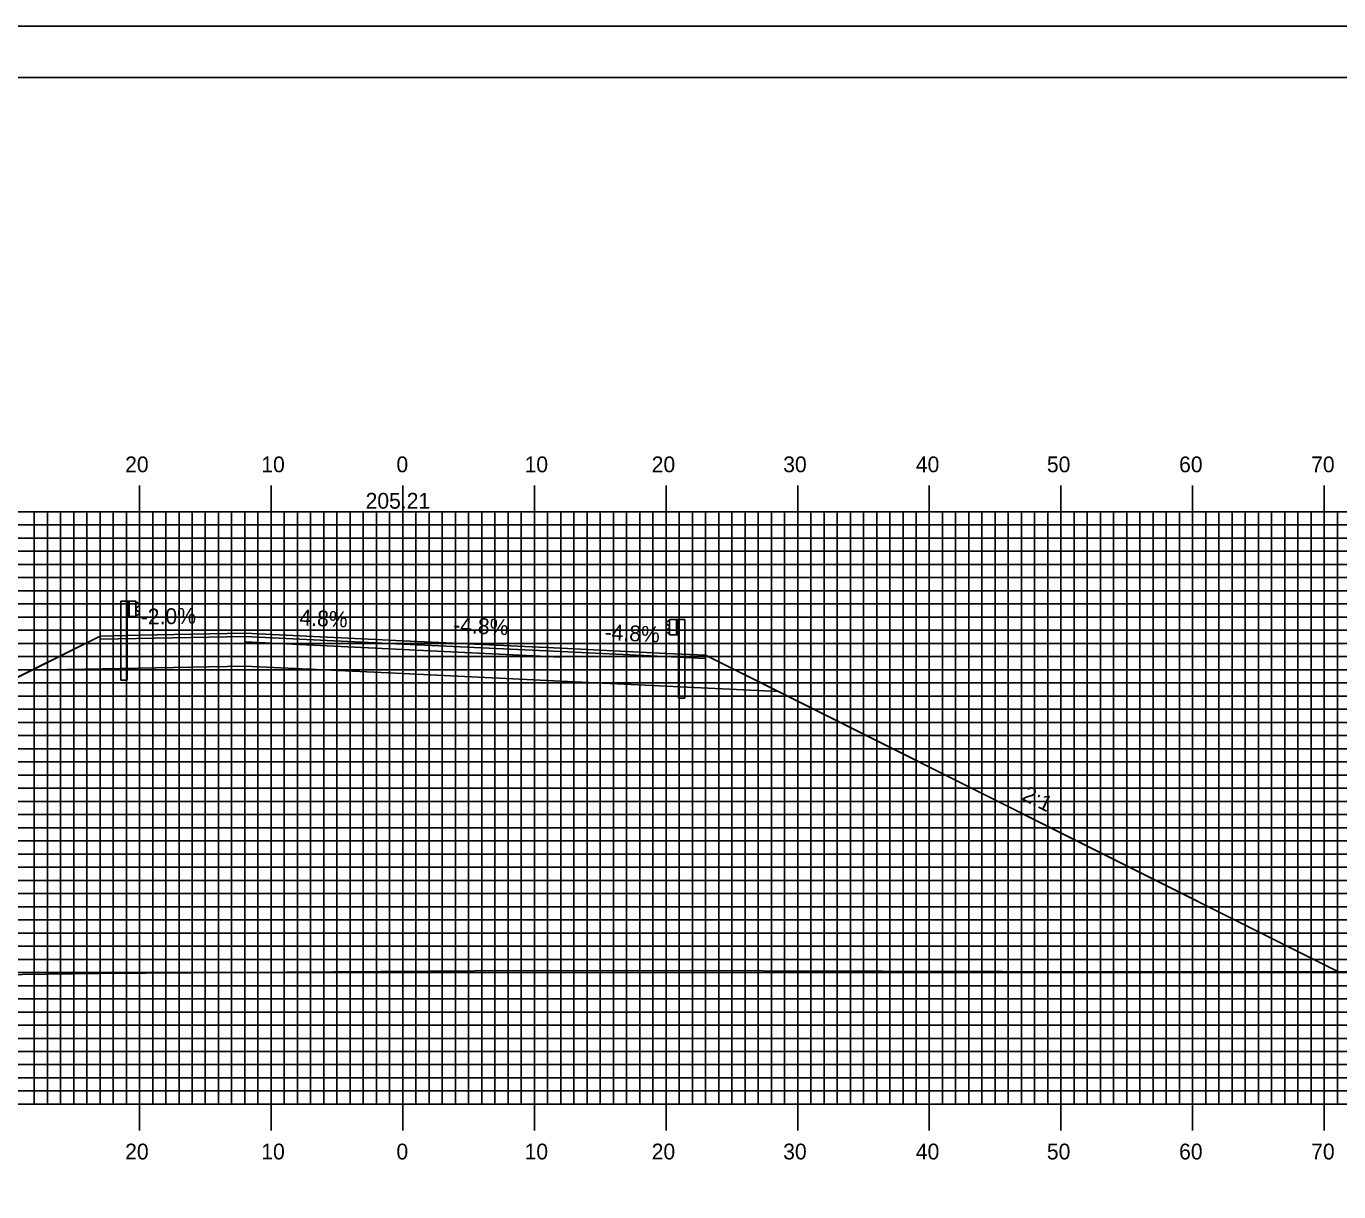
# Model space of a CAD drawing. Extents: x 1809406 to 1809749, y 442591 to 442811.
# Drawn here: x 1809543.2 to 1809642.9, y 442722 to 442810.5 of the extents above; entities that cross this region are included whole.
import ezdxf

# ---------------------------------------------------------------- set-up
doc = ezdxf.new("R2010")
doc.units = 0
for name, color, linetype in [('ANNOTATION', 7, 'Continuous'), ('BORDER', 7, 'Continuous'), ('D_Guardrail_Beam_Lt', 7, 'Continuous'), ('D_Guardrail_Beam_Rt', 7, 'Continuous'), ('D_Roadway_Centerline', 7, 'Continuous'), ('D_Roadway_Centerline_Text', 7, 'Continuous'), ('D_Roadway_Edge_Shoulder', 7, 'Continuous'), ('D_Roadway_Edge_TW', 7, 'Continuous'), ('D_Roadway_Pavement', 7, 'Continuous'), ('D_Roadway_SlopeLines', 7, 'Continuous'), ('D_Roadway_SubGrade', 7, 'Continuous'), ('H_V ANNOTATION', 7, 'Continuous'), ('MAJOR', 7, 'Continuous'), ('MINOR', 7, 'Continuous'), ('PLOT BOUNDARY', 7, 'Continuous'), ('S_Roadway_Centerline', 7, 'Continuous')]:
    doc.layers.add(name, color=color, linetype=linetype)

msp = doc.modelspace()

# ---------------------------------------------------------------- linework, layer by layer
at = {"layer": 'BORDER'}
msp.add_lwpolyline([(1809422.237, 442596.665), (1809742.237, 442596.665), (1809742.237, 442806.665), (1809422.237, 442806.665)], close=True, dxfattribs=at)
at = {"layer": 'D_Guardrail_Beam_Lt'}
for p, q in [((1809550.408, 442766.87), (1809550.408, 442760.87)), ((1809550.879, 442766.87), (1809550.408, 442766.87)), ((1809551.566, 442766.87), (1809550.879, 442766.87)), ((1809550.879, 442766.87), (1809550.879, 442765.703)), ((1809550.941, 442766.87), (1809550.941, 442765.703)), ((1809551.046, 442766.87), (1809551.046, 442765.703)), ((1809551.566, 442765.703), (1809551.566, 442766.87)), ((1809551.566, 442766.786), (1809551.641, 442766.772)), ((1809551.8, 442766.522), (1809551.605, 442766.386)), ((1809551.656, 442766.765), (1809551.8, 442766.665)), ((1809550.879, 442765.703), (1809551.566, 442765.703)), ((1809550.9, 442760.87), (1809550.9, 442765.703)), ((1809551.641, 442765.801), (1809551.566, 442765.786)), ((1809551.571, 442766.321), (1809551.571, 442766.251)), ((1809551.605, 442766.187), (1809551.8, 442766.051)), ((1809551.8, 442765.907), (1809551.656, 442765.807)), ((1809550.9, 442760.87), (1809550.408, 442760.87))]:
    msp.add_line(p, q, dxfattribs=at)
for centre, major_axis, start_param, end_param in [((1809551.633, 442766.731), (0.0417, 0), 0.959931, 1.376053), ((1809551.75, 442766.593), (0.0877, 0), 5.323254, 7.243116), ((1809551.65, 442766.321), (-0.0789, 0), 5.323254, 6.283185), ((1809551.65, 442766.251), (-0.0789, 0), 6.283185, 7.243116), ((1809551.633, 442765.841), (0.0417, 0), 4.907132, 5.323254), ((1809551.75, 442765.979), (0.0877, 0), 5.323254, 7.243116)]:
    msp.add_ellipse(centre, major_axis=major_axis, ratio=0.995501, start_param=start_param, end_param=end_param, dxfattribs=at)
at = {"layer": 'D_Guardrail_Beam_Rt'}
for p, q in [((1809592.018, 442765.389), (1809591.875, 442765.289)), ((1809591.875, 442765.146), (1809592.07, 442765.01)), ((1809592.07, 442764.811), (1809591.875, 442764.675)), ((1809591.875, 442764.531), (1809592.018, 442764.431)), ((1809592.108, 442765.41), (1809592.034, 442765.396)), ((1809592.104, 442764.945), (1809592.104, 442764.875)), ((1809592.108, 442765.494), (1809592.796, 442765.494)), ((1809592.108, 442764.327), (1809592.108, 442765.494)), ((1809592.629, 442765.494), (1809592.629, 442764.327)), ((1809592.733, 442765.494), (1809592.733, 442764.327)), ((1809592.796, 442765.494), (1809593.266, 442765.494)), ((1809592.796, 442765.494), (1809592.796, 442764.327)), ((1809593.266, 442765.494), (1809593.266, 442759.494)), ((1809592.034, 442764.425), (1809592.108, 442764.41)), ((1809592.796, 442764.327), (1809592.108, 442764.327)), ((1809592.775, 442759.494), (1809592.775, 442764.327)), ((1809592.775, 442759.494), (1809593.266, 442759.494))]:
    msp.add_line(p, q, dxfattribs=at)
for centre, major_axis, start_param, end_param in [((1809591.925, 442765.217), (-0.0877, 0), 5.323254, 7.243116), ((1809591.925, 442764.603), (-0.0877, 0), 5.323254, 7.243116), ((1809592.042, 442765.355), (-0.0417, 0), 4.907132, 5.323254), ((1809592.025, 442764.945), (0.0789, 0), 0, 0.959931), ((1809592.025, 442764.875), (0.0789, 0), 5.323254, 6.283185), ((1809592.042, 442764.465), (-0.0417, 0), 0.959931, 1.376053)]:
    msp.add_ellipse(centre, major_axis=major_axis, ratio=0.995501, start_param=start_param, end_param=end_param, dxfattribs=at)
at = {"layer": 'D_Roadway_Centerline'}
msp.add_lwpolyline([(1809497.104, 442738.36), (1809543.629, 442761.622), (1809548.837, 442764.226), (1809551.837, 442764.286), (1809559.837, 442764.446), (1809571.837, 442763.87), (1809583.837, 442763.294), (1809591.837, 442762.91), (1809594.837, 442762.766), (1809600.368, 442760.001), (1809642.88, 442738.745)], dxfattribs=at)
at = {"layer": 'D_Roadway_Edge_Shoulder'}
for points in [[(1809559.837, 442764.446), (1809551.837, 442764.286), (1809551.837, 442764.286), (1809548.837, 442764.226), (1809548.837, 442763.976), (1809559.837, 442764.196)], [(1809583.837, 442763.294), (1809591.837, 442762.91), (1809591.837, 442762.91), (1809594.837, 442762.766), (1809594.837, 442762.516), (1809583.837, 442763.044)]]:
    msp.add_lwpolyline(points, close=True, dxfattribs=at)
at = {"layer": 'D_Roadway_Edge_TW'}
msp.add_lwpolyline([(1809559.837, 442764.196), (1809559.837, 442764.446), (1809571.837, 442763.87), (1809583.837, 442763.294), (1809583.837, 442763.044), (1809571.837, 442763.62)], close=True, dxfattribs=at)
at = {"layer": 'D_Roadway_Pavement'}
msp.add_lwpolyline([(1809559.837, 442763.78), (1809559.837, 442764.196), (1809571.837, 442763.62), (1809583.837, 442763.044), (1809583.837, 442762.628), (1809571.837, 442763.204)], close=True, dxfattribs=at)
for points in [[(1809559.837, 442764.196), (1809559.837, 442763.78)], [(1809583.837, 442763.044), (1809583.837, 442762.628)]]:
    msp.add_lwpolyline(points, dxfattribs=at)
at = {"layer": 'D_Roadway_SlopeLines'}
for points in [[(1809548.837, 442764.226), (1809497.104, 442738.36)], [(1809594.837, 442762.766), (1809642.88, 442738.745)]]:
    msp.add_lwpolyline(points, dxfattribs=at)
at = {"layer": 'D_Roadway_SubGrade'}
for points in [[(1809559.837, 442763.78), (1809559.837, 442764.196), (1809548.837, 442763.976), (1809548.837, 442764.226), (1809543.629, 442761.622), (1809559.837, 442761.946)], [(1809559.837, 442761.946), (1809559.837, 442764.196), (1809559.837, 442763.78), (1809571.837, 442763.204), (1809583.837, 442762.628), (1809583.837, 442763.044), (1809583.837, 442760.794), (1809571.837, 442761.37)], [(1809583.837, 442762.628), (1809583.837, 442763.044), (1809594.837, 442762.516), (1809594.837, 442762.766), (1809600.368, 442760.001), (1809583.837, 442760.794)]]:
    msp.add_lwpolyline(points, close=True, dxfattribs=at)
at = {"layer": 'MAJOR'}
for p, q in [((1809551.837, 442775.669), (1809551.837, 442773.665)), ((1809561.837, 442775.669), (1809561.837, 442773.665)), ((1809571.837, 442775.669), (1809571.837, 442773.665)), ((1809581.837, 442775.669), (1809581.837, 442773.665)), ((1809591.837, 442775.669), (1809591.837, 442773.665)), ((1809601.837, 442775.669), (1809601.837, 442773.665)), ((1809611.837, 442775.669), (1809611.837, 442773.665)), ((1809621.837, 442775.669), (1809621.837, 442773.665)), ((1809631.837, 442775.669), (1809631.837, 442773.665)), ((1809641.837, 442775.669), (1809641.837, 442773.665)), ((1809431.837, 442773.665), (1809711.837, 442773.665)), ((1809431.837, 442773.665), (1809711.837, 442773.665)), ((1809551.837, 442728.665), (1809551.837, 442773.665)), ((1809561.837, 442728.665), (1809561.837, 442773.665)), ((1809571.837, 442728.665), (1809571.837, 442773.665)), ((1809581.837, 442728.665), (1809581.837, 442773.665)), ((1809591.837, 442728.665), (1809591.837, 442773.665)), ((1809601.837, 442728.665), (1809601.837, 442773.665)), ((1809611.837, 442728.665), (1809611.837, 442773.665)), ((1809621.837, 442728.665), (1809621.837, 442773.665)), ((1809631.837, 442728.665), (1809631.837, 442773.665)), ((1809641.837, 442728.665), (1809641.837, 442773.665)), ((1809431.837, 442768.665), (1809711.837, 442768.665)), ((1809431.837, 442763.665), (1809711.837, 442763.665)), ((1809431.837, 442758.665), (1809711.837, 442758.665)), ((1809431.837, 442753.665), (1809711.837, 442753.665)), ((1809431.837, 442748.665), (1809711.837, 442748.665)), ((1809431.837, 442743.665), (1809711.837, 442743.665)), ((1809431.837, 442738.665), (1809711.837, 442738.665)), ((1809431.837, 442733.665), (1809711.837, 442733.665)), ((1809431.837, 442728.665), (1809711.837, 442728.665)), ((1809431.837, 442728.665), (1809711.837, 442728.665)), ((1809551.837, 442726.661), (1809551.837, 442728.665)), ((1809561.837, 442726.661), (1809561.837, 442728.665)), ((1809571.837, 442726.661), (1809571.837, 442728.665)), ((1809581.837, 442726.661), (1809581.837, 442728.665)), ((1809591.837, 442726.661), (1809591.837, 442728.665)), ((1809601.837, 442726.661), (1809601.837, 442728.665)), ((1809611.837, 442726.661), (1809611.837, 442728.665)), ((1809621.837, 442726.661), (1809621.837, 442728.665)), ((1809631.837, 442726.661), (1809631.837, 442728.665)), ((1809641.837, 442726.661), (1809641.837, 442728.665))]:
    msp.add_line(p, q, dxfattribs=at)
at = {"layer": 'MINOR'}
for p, q in [((1809543.837, 442728.665), (1809543.837, 442773.665)), ((1809544.837, 442728.665), (1809544.837, 442773.665)), ((1809545.837, 442728.665), (1809545.837, 442773.665)), ((1809546.837, 442728.665), (1809546.837, 442773.665)), ((1809547.837, 442728.665), (1809547.837, 442773.665)), ((1809548.837, 442728.665), (1809548.837, 442773.665)), ((1809549.837, 442728.665), (1809549.837, 442773.665)), ((1809550.837, 442728.665), (1809550.837, 442773.665)), ((1809552.837, 442728.665), (1809552.837, 442773.665)), ((1809553.837, 442728.665), (1809553.837, 442773.665)), ((1809554.837, 442728.665), (1809554.837, 442773.665)), ((1809555.837, 442728.665), (1809555.837, 442773.665)), ((1809556.837, 442728.665), (1809556.837, 442773.665)), ((1809557.837, 442728.665), (1809557.837, 442773.665)), ((1809558.837, 442728.665), (1809558.837, 442773.665)), ((1809559.837, 442728.665), (1809559.837, 442773.665)), ((1809560.837, 442728.665), (1809560.837, 442773.665)), ((1809562.837, 442728.665), (1809562.837, 442773.665)), ((1809563.837, 442728.665), (1809563.837, 442773.665)), ((1809564.837, 442728.665), (1809564.837, 442773.665)), ((1809565.837, 442728.665), (1809565.837, 442773.665)), ((1809566.837, 442728.665), (1809566.837, 442773.665)), ((1809567.837, 442728.665), (1809567.837, 442773.665)), ((1809568.837, 442728.665), (1809568.837, 442773.665)), ((1809569.837, 442728.665), (1809569.837, 442773.665)), ((1809570.837, 442728.665), (1809570.837, 442773.665)), ((1809572.837, 442728.665), (1809572.837, 442773.665)), ((1809573.837, 442728.665), (1809573.837, 442773.665)), ((1809574.837, 442728.665), (1809574.837, 442773.665)), ((1809575.837, 442728.665), (1809575.837, 442773.665)), ((1809576.837, 442728.665), (1809576.837, 442773.665)), ((1809577.837, 442728.665), (1809577.837, 442773.665)), ((1809578.837, 442728.665), (1809578.837, 442773.665)), ((1809579.837, 442728.665), (1809579.837, 442773.665)), ((1809580.837, 442728.665), (1809580.837, 442773.665)), ((1809582.837, 442728.665), (1809582.837, 442773.665)), ((1809583.837, 442728.665), (1809583.837, 442773.665)), ((1809584.837, 442728.665), (1809584.837, 442773.665)), ((1809585.837, 442728.665), (1809585.837, 442773.665)), ((1809586.837, 442728.665), (1809586.837, 442773.665)), ((1809587.837, 442728.665), (1809587.837, 442773.665)), ((1809588.837, 442728.665), (1809588.837, 442773.665)), ((1809589.837, 442728.665), (1809589.837, 442773.665)), ((1809590.837, 442728.665), (1809590.837, 442773.665)), ((1809592.837, 442728.665), (1809592.837, 442773.665)), ((1809593.837, 442728.665), (1809593.837, 442773.665)), ((1809594.837, 442728.665), (1809594.837, 442773.665)), ((1809595.837, 442728.665), (1809595.837, 442773.665)), ((1809596.837, 442728.665), (1809596.837, 442773.665)), ((1809597.837, 442728.665), (1809597.837, 442773.665)), ((1809598.837, 442728.665), (1809598.837, 442773.665)), ((1809599.837, 442728.665), (1809599.837, 442773.665)), ((1809600.837, 442728.665), (1809600.837, 442773.665)), ((1809602.837, 442728.665), (1809602.837, 442773.665)), ((1809603.837, 442728.665), (1809603.837, 442773.665)), ((1809604.837, 442728.665), (1809604.837, 442773.665)), ((1809605.837, 442728.665), (1809605.837, 442773.665)), ((1809606.837, 442728.665), (1809606.837, 442773.665)), ((1809607.837, 442728.665), (1809607.837, 442773.665)), ((1809608.837, 442728.665), (1809608.837, 442773.665)), ((1809609.837, 442728.665), (1809609.837, 442773.665)), ((1809610.837, 442728.665), (1809610.837, 442773.665)), ((1809612.837, 442728.665), (1809612.837, 442773.665)), ((1809613.837, 442728.665), (1809613.837, 442773.665)), ((1809614.837, 442728.665), (1809614.837, 442773.665)), ((1809615.837, 442728.665), (1809615.837, 442773.665)), ((1809616.837, 442728.665), (1809616.837, 442773.665)), ((1809617.837, 442728.665), (1809617.837, 442773.665)), ((1809618.837, 442728.665), (1809618.837, 442773.665)), ((1809619.837, 442728.665), (1809619.837, 442773.665)), ((1809620.837, 442728.665), (1809620.837, 442773.665)), ((1809622.837, 442728.665), (1809622.837, 442773.665)), ((1809623.837, 442728.665), (1809623.837, 442773.665)), ((1809624.837, 442728.665), (1809624.837, 442773.665)), ((1809625.837, 442728.665), (1809625.837, 442773.665)), ((1809626.837, 442728.665), (1809626.837, 442773.665)), ((1809627.837, 442728.665), (1809627.837, 442773.665)), ((1809628.837, 442728.665), (1809628.837, 442773.665)), ((1809629.837, 442728.665), (1809629.837, 442773.665)), ((1809630.837, 442728.665), (1809630.837, 442773.665)), ((1809632.837, 442728.665), (1809632.837, 442773.665)), ((1809633.837, 442728.665), (1809633.837, 442773.665)), ((1809634.837, 442728.665), (1809634.837, 442773.665)), ((1809635.837, 442728.665), (1809635.837, 442773.665)), ((1809636.837, 442728.665), (1809636.837, 442773.665)), ((1809637.837, 442728.665), (1809637.837, 442773.665)), ((1809638.837, 442728.665), (1809638.837, 442773.665)), ((1809639.837, 442728.665), (1809639.837, 442773.665)), ((1809640.837, 442728.665), (1809640.837, 442773.665)), ((1809642.837, 442728.665), (1809642.837, 442773.665)), ((1809431.837, 442772.665), (1809711.837, 442772.665)), ((1809431.837, 442771.665), (1809711.837, 442771.665)), ((1809431.837, 442770.665), (1809711.837, 442770.665)), ((1809431.837, 442769.665), (1809711.837, 442769.665)), ((1809431.837, 442767.665), (1809711.837, 442767.665)), ((1809431.837, 442766.665), (1809711.837, 442766.665)), ((1809431.837, 442765.665), (1809711.837, 442765.665)), ((1809431.837, 442764.665), (1809711.837, 442764.665)), ((1809431.837, 442762.665), (1809711.837, 442762.665)), ((1809431.837, 442761.665), (1809711.837, 442761.665)), ((1809431.837, 442760.665), (1809711.837, 442760.665)), ((1809431.837, 442759.665), (1809711.837, 442759.665)), ((1809431.837, 442757.665), (1809711.837, 442757.665)), ((1809431.837, 442756.665), (1809711.837, 442756.665)), ((1809431.837, 442755.665), (1809711.837, 442755.665)), ((1809431.837, 442754.665), (1809711.837, 442754.665)), ((1809431.837, 442752.665), (1809711.837, 442752.665)), ((1809431.837, 442751.665), (1809711.837, 442751.665)), ((1809431.837, 442750.665), (1809711.837, 442750.665)), ((1809431.837, 442749.665), (1809711.837, 442749.665)), ((1809431.837, 442747.665), (1809711.837, 442747.665)), ((1809431.837, 442746.665), (1809711.837, 442746.665)), ((1809431.837, 442745.665), (1809711.837, 442745.665)), ((1809431.837, 442744.665), (1809711.837, 442744.665)), ((1809431.837, 442742.665), (1809711.837, 442742.665)), ((1809431.837, 442741.665), (1809711.837, 442741.665)), ((1809431.837, 442740.665), (1809711.837, 442740.665)), ((1809431.837, 442739.665), (1809711.837, 442739.665)), ((1809431.837, 442737.665), (1809711.837, 442737.665)), ((1809431.837, 442736.665), (1809711.837, 442736.665)), ((1809431.837, 442735.665), (1809711.837, 442735.665)), ((1809431.837, 442734.665), (1809711.837, 442734.665)), ((1809431.837, 442732.665), (1809711.837, 442732.665)), ((1809431.837, 442731.665), (1809711.837, 442731.665)), ((1809431.837, 442730.665), (1809711.837, 442730.665)), ((1809431.837, 442729.665), (1809711.837, 442729.665))]:
    msp.add_line(p, q, dxfattribs=at)
at = {"layer": 'PLOT BOUNDARY'}
msp.add_lwpolyline([(1809406.051, 442590.547), (1809746.051, 442590.547), (1809746.051, 442810.547), (1809406.051, 442810.547)], close=True, dxfattribs=at)
at = {"layer": 'S_Roadway_Centerline'}
msp.add_lwpolyline([(1809431.837, 442738.372), (1809434.294, 442738.361), (1809434.645, 442738.298), (1809452.597, 442737.803), (1809467.848, 442737.87), (1809488.356, 442738.445), (1809500.772, 442738.324), (1809523.635, 442738.263), (1809548.727, 442738.592), (1809580.875, 442738.827), (1809599.226, 442738.793), (1809626.496, 442738.723), (1809646.176, 442738.749), (1809689.653, 442738.546), (1809701.874, 442738.54), (1809705.766, 442738.661), (1809711.837, 442738.758)], dxfattribs=at)

# ---------------------------------------------------------------- texts
at = {"layer": 'ANNOTATION'}
for s, rotation, p in [('-2.0%', 1.14576, (1809551.943, 442765.089)), ('4.8%', 357.25191, (1809563.966, 442765.05)), ('-4.8%', 357.25191, (1809575.646, 442764.49)), ('-4.8%', 357.25191, (1809587.146, 442763.938)), ('2:1', 333.43495, (1809618.793, 442751.825))]:
    msp.add_text(s, height=1.2, rotation=rotation, dxfattribs=at).set_placement(p)
at = {"layer": 'D_Roadway_Centerline'}
for s, p in [('C', (1809571.832, 442763.87)), ('L', (1809571.837, 442763.863))]:
    msp.add_text(s, height=0.0146, dxfattribs=at).set_placement(p)
at = {"layer": 'D_Roadway_Centerline_Text'}
msp.add_text('205.21', height=1.2, dxfattribs=at).set_placement((1809569.012, 442773.9))
at = {"layer": 'H_V ANNOTATION'}
for s, p in [('20', (1809550.745, 442776.665)), ('10', (1809561.088, 442776.665)), ('0', (1809571.355, 442776.665)), ('10', (1809581.088, 442776.665)), ('20', (1809590.745, 442776.665)), ('30', (1809600.735, 442776.665)), ('40', (1809610.81, 442776.665)), ('50', (1809620.767, 442776.665)), ('60', (1809630.81, 442776.665)), ('70', (1809640.841, 442776.665)), ('20', (1809550.745, 442724.465)), ('10', (1809561.088, 442724.465)), ('0', (1809571.355, 442724.465)), ('10', (1809581.088, 442724.465)), ('20', (1809590.745, 442724.465)), ('30', (1809600.735, 442724.465)), ('40', (1809610.81, 442724.465)), ('50', (1809620.767, 442724.465)), ('60', (1809630.81, 442724.465)), ('70', (1809640.841, 442724.465))]:
    msp.add_text(s, height=1.2, dxfattribs=at).set_placement(p)

doc.saveas('drawing.dxf')
